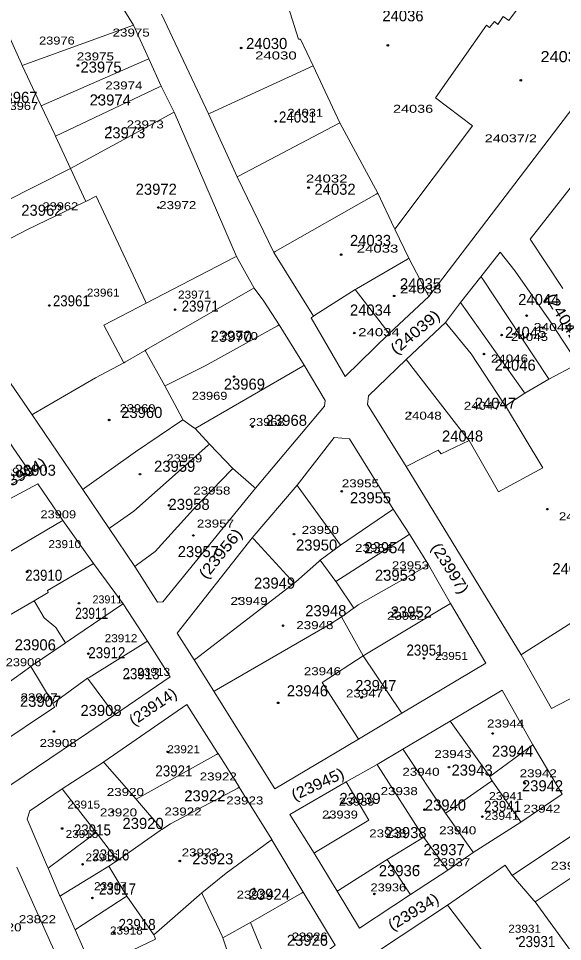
# Model space of a CAD drawing. Extents: x 649608 to 651081, y 237980 to 241202.
# Drawn here: x 650649.6 to 650826.5, y 238207.6 to 238507.5 of the extents above; entities that cross this region are included whole.
import ezdxf

# ---------------------------------------------------------------- set-up
doc = ezdxf.new("R2010")
doc.units = 0
doc.header["$PDMODE"] = 32
doc.header["$PDSIZE"] = 0.5
for name, color, linetype in [('19', 7, 'Continuous'), ('20', 7, 'Continuous'), ('6', 7, 'Continuous')]:
    doc.layers.add(name, color=color, linetype=linetype)
doc.layers.add('3', color=7, linetype='Continuous', lineweight=13)
doc.layers.add('5', color=7, linetype='Continuous', lineweight=13)

msp = doc.modelspace()

# ---------------------------------------------------------------- linework, layer by layer
at = {"layer": '3'}
for p, q in [((650698.955, 238293.605), (650680.881, 238281.304)), ((650833.028, 238244.372), (650810.115, 238229.097))]:
    msp.add_line(p, q, dxfattribs=at)
for points in [[(650687.044, 238505.407), (650681.393, 238514.544), (650666.233, 238537.335), (650662.489, 238538.449), (650636.452, 238531.69), (650637.963, 238526.941), (650615.232, 238519.416)], [(650856.496, 238513.231), (650783.062, 238417.168), (650770.127, 238405.165)], [(650770.127, 238405.165), (650755.807, 238391.194), (650744.776, 238410.239), (650745.518, 238410.844), (650732.624, 238431.532), (650720.683, 238456.081), (650711.443, 238476.563), (650696.151, 238508.876)], [(650734.391, 238407.977), (650729.447, 238415.682), (650726.234, 238419.926), (650720.477, 238430.206), (650700.272, 238477.13), (650695.994, 238485.566), (650691.998, 238494.43), (650687.044, 238505.407)], [(650573.208, 238503.022), (650582.152, 238488.127), (650590.385, 238475.32), (650600.043, 238460.139), (650617.299, 238433.842), (650623.21, 238423.714), (650654.029, 238378.774), (650670.572, 238354.523), (650679.086, 238341.791), (650687.498, 238329.514), (650694.786, 238317.819)], [(650826.605, 238419.813), (650815.978, 238435.816), (650831.358, 238455.416)], [(650775.665, 238361.941), (650763.101, 238382.048), (650763.388, 238384.951), (650775.735, 238396.677), (650788.491, 238408.706), (650793.362, 238415.29), (650800.026, 238423.614), (650806.229, 238431.585)], [(650806.229, 238431.585), (650811.125, 238425.42), (650822.189, 238409.657), (650831.543, 238395.385)], [(650613.787, 238417.512), (650614.114, 238417.034), (650626.967, 238398.087), (650637.752, 238383.107), (650643.512, 238374.619), (650647.922, 238368.026), (650653.658, 238359.639), (650629.394, 238346.511)], [(650726.691, 238354.921), (650749.09, 238381.608), (650749.4, 238383.4), (650742.572, 238394.867), (650734.391, 238407.977)], [(650740.192, 238355.867), (650752.316, 238371.38), (650757.249, 238370.921), (650771.495, 238348.086), (650776.796, 238339.927), (650782.989, 238330), (650790.096, 238317.421)], [(650854.104, 238299.459), (650822.931, 238283.334), (650813.072, 238300.813), (650775.665, 238361.941)], [(650625.649, 238340.229), (650655.926, 238356.355), (650664.083, 238344.431), (650674, 238330.436), (650683.612, 238317.325), (650691.539, 238305.2), (650698.955, 238293.605)], [(650694.786, 238317.819), (650696.602, 238318.019), (650726.691, 238354.921)], [(650701.208, 238307.79), (650725.636, 238338.817), (650740.192, 238355.867)], [(650790.096, 238317.421), (650801.562, 238298.098), (650774.25, 238281.767), (650760.146, 238273.349)], [(650760.146, 238273.349), (650732.936, 238257.22), (650713.263, 238288.77), (650713.175, 238288.91), (650706.764, 238299.126), (650701.208, 238307.79)], [(650680.881, 238281.304), (650647.164, 238258.567), (650641.308, 238270.413), (650635.299, 238282.662), (650625.495, 238302.287)], [(650789.994, 238279.252), (650806.913, 238289.232), (650816.899, 238271.551)], [(650714.531, 238268.662), (650714.348, 238268.952), (650704.332, 238284.588), (650677.373, 238266.01), (650677.247, 238265.929)], [(650737.828, 238248.885), (650756.181, 238259.444), (650766.239, 238265.088), (650774.635, 238270.154), (650789.994, 238279.252)], [(650816.899, 238271.551), (650826.377, 238255.436), (650812.988, 238246.437), (650797.501, 238236.582), (650789.282, 238230.759), (650777.071, 238222.869)], [(650721.411, 238257.749), (650721.356, 238257.837), (650714.531, 238268.662)], [(650677.247, 238265.929), (650663.78, 238257.263), (650663.772, 238257.257)], [(650663.772, 238257.257), (650653.334, 238250.104), (650652.459, 238247.354), (650658.999, 238231.898), (650659.214, 238231.401)], [(650731.986, 238240.663), (650731.957, 238240.711), (650721.411, 238257.749)], [(650777.071, 238222.869), (650760.508, 238211.93), (650753.271, 238223.978), (650745.728, 238236.33), (650737.828, 238248.885)], [(650733.752, 238192.67), (650752.648, 238206.409), (650742.2, 238223.611), (650731.986, 238240.663)], [(650649.081, 238231.778), (650661.143, 238204.909), (650661.217, 238204.732)], [(650659.214, 238231.401), (650662.994, 238222.68), (650663.128, 238222.38), (650668.008, 238211.416), (650673.734, 238198.611)], [(650810.115, 238229.097), (650807.908, 238232.424), (650789.131, 238219.424)], [(650789.131, 238219.424), (650766.398, 238204.401), (650792.759, 238167.518), (650815.522, 238184.763), (650833.498, 238198.629)]]:
    msp.add_lwpolyline(points, dxfattribs=at)
at = {"layer": '5'}
for p, q in [((650666.513, 238458.735), (650661.677, 238469.292)), ((650666.513, 238458.735), (650644.862, 238447.851)), ((650674.685, 238390.795), (650683.873, 238395.683))]:
    msp.add_line(p, q, dxfattribs=at)
for points in [[(650716.197, 238514.45), (650716.697, 238514.578), (650735.331, 238519.332), (650737.208, 238511.711), (650740.707, 238500.782), (650741.379, 238500.793), (650745.427, 238492.156)], [(650815.76, 238515.874), (650815.392, 238515.374), (650809.118, 238506.861), (650807.289, 238508.15), (650805.53, 238505.605), (650804.445, 238506.55), (650802.807, 238504.638), (650801.776, 238505.381)], [(650656.967, 238479.117), (650656.732, 238479.617), (650650.781, 238492.275), (650687.044, 238505.407)], [(650801.776, 238505.381), (650785.213, 238481.741), (650797.262, 238472.641), (650771.985, 238439.041), (650776.594, 238429.62)], [(650650.781, 238492.275), (650650.557, 238492.775), (650646.354, 238502.163), (650647.011, 238502.484)], [(650656.967, 238479.117), (650691.498, 238494.211), (650691.998, 238494.43)], [(650745.427, 238492.156), (650711.943, 238476.792), (650711.443, 238476.563)], [(650771.985, 238439.041), (650771.748, 238439.541), (650766.436, 238450.76), (650754.133, 238473.618), (650745.427, 238492.156)], [(650661.677, 238469.292), (650695.494, 238485.329), (650695.994, 238485.566)], [(650661.677, 238469.292), (650661.437, 238469.792), (650656.967, 238479.117)], [(650700.272, 238477.13), (650699.772, 238476.858), (650666.513, 238458.735), (650671.477, 238448.077)], [(650754.133, 238473.618), (650753.633, 238473.356), (650721.183, 238456.343), (650720.683, 238456.081)], [(650671.477, 238448.077), (650674.855, 238449.74), (650690.912, 238415.563), (650691.147, 238415.063)], [(650766.436, 238450.76), (650765.936, 238450.476), (650733.124, 238431.816), (650732.624, 238431.532)], [(650671.477, 238448.077), (650670.977, 238447.836), (650652.591, 238438.983), (650623.71, 238423.974), (650623.21, 238423.714)], [(650691.147, 238415.063), (650719.977, 238429.948), (650720.477, 238430.206)], [(650776.594, 238429.62), (650776.094, 238429.329), (650759.56, 238419.704), (650759.06, 238419.413)], [(650776.594, 238429.62), (650782.802, 238417.668), (650783.062, 238417.168)], [(650822.125, 238390.345), (650821.793, 238390.845), (650800.358, 238423.114), (650800.026, 238423.614)], [(650690.784, 238399.665), (650691.284, 238399.951), (650725.734, 238419.64), (650726.234, 238419.926)], [(650759.06, 238419.413), (650746.018, 238411.16), (650745.518, 238410.844)], [(650770.127, 238405.165), (650769.739, 238405.665), (650759.06, 238419.413)], [(650683.873, 238395.683), (650677.378, 238407.882), (650691.147, 238415.063)], [(650814.267, 238385.733), (650813.913, 238386.233), (650793.716, 238414.79), (650793.362, 238415.29)], [(650697.254, 238388.122), (650697.754, 238388.371), (650710.306, 238394.622), (650733.891, 238407.7), (650734.391, 238407.977)], [(650807.944, 238381.701), (650807.612, 238382.201), (650796.779, 238398.524), (650788.898, 238408.206), (650788.491, 238408.706)], [(650683.873, 238395.683), (650684.373, 238395.971), (650690.784, 238399.665), (650697.254, 238388.122)], [(650796.135, 238370.378), (650795.747, 238370.878), (650776.123, 238396.177), (650775.735, 238396.677)], [(650831.543, 238395.385), (650831.043, 238395.117), (650822.125, 238390.345), (650814.267, 238385.733), (650807.944, 238381.701)], [(650742.572, 238394.867), (650742.072, 238394.578), (650707.018, 238374.328), (650711.712, 238369.224), (650719.315, 238361.29)], [(650674.685, 238390.795), (650654.529, 238379.065), (650654.029, 238378.774)], [(650697.254, 238388.122), (650702.797, 238377.609), (650703.061, 238377.109)], [(650807.944, 238381.701), (650820.149, 238361.544), (650805.688, 238353.757), (650796.135, 238370.378)], [(650703.061, 238377.109), (650687.624, 238366.673), (650671.072, 238354.879), (650670.572, 238354.523)], [(650707.018, 238374.328), (650706.518, 238374.679), (650703.061, 238377.109)], [(650711.712, 238369.224), (650711.212, 238368.78), (650687.176, 238347.413), (650679.586, 238342.138), (650679.086, 238341.791)], [(650796.135, 238370.378), (650787.024, 238366.12), (650786.132, 238367.257), (650776.165, 238362.195), (650775.665, 238361.941)], [(650719.315, 238361.29), (650718.83, 238360.79), (650706.531, 238348.1), (650694.078, 238334.304), (650687.998, 238329.878), (650687.498, 238329.514)], [(650719.315, 238361.29), (650726.191, 238355.353), (650726.691, 238354.921)], [(650740.192, 238355.867), (650740.556, 238355.367), (650754.367, 238336.415)], [(650754.367, 238336.415), (650770.995, 238347.745), (650771.495, 238348.086)], [(650633.06, 238326.261), (650633.56, 238326.554), (650663.583, 238344.138), (650664.083, 238344.431)], [(650725.636, 238338.817), (650726.098, 238338.317), (650739.284, 238324.06)], [(650752.861, 238324.602), (650776.296, 238339.607), (650776.796, 238339.927)], [(650754.367, 238336.415), (650753.867, 238336.048), (650747.736, 238331.55), (650752.861, 238324.602)], [(650654.699, 238318.288), (650659.301, 238321.036), (650659.009, 238321.678), (650673.5, 238330.144), (650674, 238330.436)], [(650739.284, 238324.06), (650739.784, 238324.503), (650747.236, 238331.107), (650747.736, 238331.55)], [(650758.672, 238315.938), (650760.081, 238317.047), (650782.489, 238329.717), (650782.989, 238330)], [(650739.284, 238324.06), (650707.264, 238299.509), (650706.764, 238299.126)], [(650752.861, 238324.602), (650753.196, 238324.102), (650758.672, 238315.938)], [(650642.003, 238311.005), (650642.503, 238311.292), (650654.699, 238318.288)], [(650654.699, 238318.288), (650654.997, 238317.788), (650657.986, 238312.781), (650661.789, 238309.622), (650664.923, 238304.62)], [(650664.923, 238304.62), (650683.112, 238316.985), (650683.612, 238317.325)], [(650790.096, 238317.421), (650789.596, 238317.128), (650786.052, 238315.052), (650761.76, 238300.46)], [(650842.562, 238319.464), (650842.062, 238319.148), (650813.572, 238301.129), (650813.072, 238300.813)], [(650758.672, 238315.938), (650758.172, 238315.584), (650755.178, 238313.468), (650754.678, 238313.114)], [(650713.175, 238288.91), (650713.302, 238288.983), (650751.299, 238310.921), (650754.678, 238313.114), (650761.76, 238300.46)], [(650672.084, 238293.127), (650672.584, 238293.437), (650691.039, 238304.89), (650691.539, 238305.2)], [(650664.923, 238304.62), (650664.423, 238304.283), (650654.096, 238297.323), (650653.596, 238296.986)], [(650761.76, 238300.46), (650748.371, 238291.789), (650759.827, 238273.849), (650760.146, 238273.349)], [(650774.25, 238281.767), (650773.916, 238282.267), (650761.76, 238300.46)], [(650635.299, 238282.662), (650635.799, 238283.032), (650646.025, 238290.6), (650645.528, 238291.118), (650653.596, 238296.986)], [(650653.596, 238296.986), (650660.519, 238285.434), (650660.819, 238284.934)], [(650641.308, 238270.413), (650641.808, 238270.746), (650661.302, 238283.747), (650660.819, 238284.934), (650672.084, 238293.127)], [(650672.084, 238293.127), (650680.509, 238281.804), (650680.881, 238281.304)], [(650802.849, 238261.186), (650790.35, 238278.752), (650789.994, 238279.252)], [(650774.635, 238270.154), (650774.966, 238269.654), (650788.476, 238249.263)], [(650816.899, 238271.551), (650816.399, 238271.182), (650802.849, 238261.186)], [(650687.856, 238253.857), (650714.031, 238268.384), (650714.531, 238268.662)], [(650677.247, 238265.929), (650677.686, 238265.429), (650687.856, 238253.857)], [(650766.239, 238265.088), (650766.56, 238264.588), (650781.429, 238241.445)], [(650802.849, 238261.186), (650803.13, 238260.686), (650803.614, 238259.825)], [(650674.898, 238243.015), (650664.163, 238256.757), (650663.772, 238257.257)], [(650721.411, 238257.749), (650720.911, 238257.484), (650699.038, 238245.894), (650696.273, 238243.978), (650696.203, 238244.06)], [(650756.181, 238259.444), (650756.476, 238258.944), (650763.518, 238246.991), (650746.228, 238236.63), (650745.728, 238236.33)], [(650803.614, 238259.825), (650803.114, 238259.476), (650788.976, 238249.612), (650788.476, 238249.263)], [(650803.614, 238259.825), (650812.638, 238246.937), (650812.988, 238246.437)], [(650696.203, 238244.06), (650688.282, 238253.357), (650687.856, 238253.857)], [(650788.476, 238249.263), (650797.145, 238237.082), (650797.501, 238236.582)], [(650659.214, 238231.401), (650659.714, 238231.771), (650674.898, 238243.015)], [(650681.808, 238233.895), (650675.277, 238242.515), (650674.898, 238243.015)], [(650696.203, 238244.06), (650695.703, 238243.707), (650681.808, 238233.895)], [(650731.986, 238240.663), (650731.486, 238240.3), (650717.107, 238229.871), (650709.194, 238223.416), (650693.647, 238209.825), (650684.852, 238222.355)], [(650781.429, 238241.445), (650780.929, 238241.142), (650769.475, 238234.211)], [(650781.429, 238241.445), (650788.915, 238231.259), (650789.282, 238230.759)], [(650681.808, 238233.895), (650681.308, 238233.576), (650678.984, 238232.092)], [(650769.475, 238234.211), (650768.975, 238233.895), (650753.771, 238224.294), (650753.271, 238223.978)], [(650769.475, 238234.211), (650776.736, 238223.369), (650777.071, 238222.869)], [(650678.984, 238232.092), (650678.966, 238232.08), (650663.628, 238222.686), (650663.128, 238222.38)], [(650684.852, 238222.355), (650679.285, 238231.592), (650678.984, 238232.092)], [(650817.634, 238220.462), (650829.028, 238228.095), (650831.481, 238224.416), (650841.05, 238231.01), (650841.55, 238231.355)], [(650817.634, 238220.462), (650817.199, 238220.962), (650810.55, 238228.597), (650810.115, 238229.097)], [(650684.852, 238222.355), (650684.352, 238222.03), (650668.508, 238211.741), (650668.008, 238211.416)], [(650716.041, 238208.793), (650715.807, 238209.293), (650709.428, 238222.916), (650709.194, 238223.416)], [(650742.2, 238223.611), (650741.7, 238223.325), (650725.102, 238213.833)], [(650815.522, 238184.763), (650815.141, 238185.263), (650789.512, 238218.924), (650789.131, 238219.424)], [(650833.498, 238198.629), (650833.135, 238199.129), (650817.634, 238220.462)], [(650725.102, 238213.833), (650724.602, 238213.555), (650716.041, 238208.793)], [(650725.102, 238213.833), (650733.548, 238193.17), (650733.752, 238192.67)], [(650673.734, 238198.611), (650674.234, 238198.851), (650694.13, 238208.411), (650693.818, 238209.325), (650693.647, 238209.825)], [(650716.041, 238208.793), (650723.624, 238186.162), (650723.792, 238185.662)]]:
    msp.add_lwpolyline(points, dxfattribs=at)
at = {"layer": '6'}
for p in [(650722.018, 238497.947), (650769.738, 238498.79), (650668.913, 238492.262), (650812.989, 238487.434), (650675.713, 238481.861), (650733.222, 238474.118), (650679.418, 238472.15), (650743.924, 238452.575), (650695.101, 238446.096), (650754.547, 238430.802), (650771.788, 238417.392), (650659.648, 238414.257), (650700.551, 238412.944), (650814.85, 238410.965), (650712.836, 238404.024), (650758.827, 238405.303), (650806.739, 238404.673), (650801.019, 238398.495), (650719.74, 238391.152), (650797.972, 238381.231), (650679.107, 238377.094), (650777.01, 238379.309), (650725.726, 238374.894), (650689.102, 238359.45), (650754.748, 238353.897), (650698.569, 238349.369), (650821.623, 238348.099), (650706.489, 238339.554), (650739.198, 238339.963), (650762.735, 238336.344), (650652.447, 238327.718), (650768.697, 238327.932), (650669.308, 238317.528), (650721.329, 238318.971), (650772.013, 238315.23), (650735.674, 238310.23), (650672.361, 238301.129), (650781.506, 238299.594), (650685.361, 238293.252), (650761.154, 238286.904), (650734.055, 238285.167), (650661.123, 238275.847), (650803.852, 238275.209), (650698.105, 238269.222), (650789.603, 238264.257), (650814.24, 238258.994), (650705.504, 238256.32), (650680.364, 238249.912), (650750.723, 238247.887), (650781.663, 238250.456), (650800.491, 238248.203), (650663.805, 238244.329), (650769.431, 238244.533), (650702.072, 238233.787), (650670.448, 238232.697), (650779.553, 238232.157), (650726.167, 238224.728), (650673.667, 238221.754), (650765.376, 238223.07), (650680.805, 238210.483), (650739.513, 238208.14), (650811.818, 238208.593)]:
    msp.add_point(p, dxfattribs=at)

# ---------------------------------------------------------------- texts
at = {"layer": '19'}
for s, p in [('24036', (650767.957, 238506.6)), ('24030', (650723.63, 238497.601)), ('23975', (650669.764, 238489.921)), ('23967', (650642.402, 238480.109)), ('23974', (650672.756, 238479.256)), ('23973', (650677.459, 238468.591)), ('23972', (650687.719, 238450.247)), ('24032', (650745.861, 238450.248)), ('23962', (650650.525, 238443.421)), ('24033', (650757.403, 238433.61)), ('24035', (650773.649, 238419.532)), ('24044', (650812.123, 238414.411)), ('24034', (650757.403, 238411)), ('24045', (650807.849, 238403.746)), ('23970', (650712.088, 238402.466)), ('24046', (650804.429, 238393.081)), ('23969', (650716.386, 238386.917)), ('24047', (650798.016, 238380.709)), ('23960', (650683.016, 238377.723)), ('23968', (650730.042, 238375.163)), ('24048', (650787.329, 238370.044)), ('23903', (650648.388, 238358.951)), ('23959', (650693.704, 238360.232)), ('23955', (650757.404, 238349.992)), ('23958', (650698.406, 238347.86)), ('23950', (650739.875, 238334.634)), ('23957', (650701.399, 238332.502)), ('23954', (650762.105, 238333.781)), ('24049', (650823.24, 238326.956)), ('23953', (650765.527, 238324.822)), ('23949', (650726.196, 238322.262)), ('23948', (650742.867, 238313.304)), ('23952', (650770.657, 238312.877)), ('23906', (650648.388, 238302.212)), ('23946', (650736.883, 238287.281)), ('23947', (650759.114, 238288.987)), ('23907', (650650.098, 238283.868)), ('23908', (650669.763, 238280.882)), ('23944', (650803.574, 238267.657)), ('23943', (650790.437, 238261.501)), ('23942', (650813.349, 238256.412)), ('23922', (650703.538, 238253.153)), ('23939', (650753.983, 238252.299)), ('23940', (650781.771, 238250.166)), ('23920', (650683.444, 238244.194)), ('23938', (650768.946, 238241.208)), ('23937', (650781.344, 238235.662)), ('23923', (650706.103, 238232.676)), ('23936', (650766.808, 238228.836)), ('23924', (650724.485, 238221.157)), ('23926', (650736.883, 238206.226))]:
    msp.add_text(s, height=3.6, dxfattribs=at).set_placement(p)
for s, width, p in [('24037/2', 1.1, (650819.392, 238493.334)), ('24031', 0.9, (650734.318, 238473.711)), ('23961', 0.9, (650660.785, 238413.985)), ('23971', 0.9, (650702.682, 238412.278)), ('23910', 0.9, (650651.807, 238324.822)), ('23911', 0.8, (650668.054, 238312.451)), ('23912', 0.9, (650672.329, 238299.652)), ('23951', 0.9, (650775.787, 238300.505)), ('23913', 0.9, (650683.444, 238292.827)), ('23921', 0.9, (650694.132, 238261.258)), ('23941', 0.9, (650801.01, 238249.74)), ('23915', 0.9, (650667.626, 238242.061)), ('23916', 0.9, (650673.611, 238233.955)), ('23917', 0.9, (650675.748, 238222.864)), ('23918', 0.9, (650682.161, 238211.345)), ('23931', 0.9, (650812.124, 238205.799))]:
    msp.add_text(s, height=3.6, dxfattribs=dict(at, width=width)).set_placement(p)
for s, rotation, width, p in [('(24042)', 301.484, 1.15, (650820.818, 238416.872)), ('(24039)', 40.043, 1.15, (650772.436, 238398.14)), ('(23904)', 29.304, 1.1, (650643.18, 238353.038)), ('(23956)', 51.277, 1.15, (650710.7, 238325.097)), ('(23997)', 301.854, 1.1, (650783.644, 238335.703)), ('(23914)', 34.121, 1.05, (650687.09, 238277.572)), ('(23945)', 24.73, 1.1, (650739.37, 238253.303)), ('(23934)', 31.21, 1.1, (650771.138, 238211.032))]:
    msp.add_text(s, height=3.6, rotation=rotation, dxfattribs=dict(at, width=width)).set_placement(p)
at = {"layer": '20'}
for s, width, p in [('23975', 1.25, (650680.217, 238501.643)), ('23976', 1.2, (650656.298, 238499.049)), ('23975', 1.25, (650668.579, 238493.894)), ('24030 ', 1.4, (650726.556, 238494.211)), ('23974', 1.25, (650677.852, 238484.474)), ('23967', 1.2, (650644.394, 238477.799)), ('24036 ', 1.35, (650771.42, 238476.881)), ('24031 ', 1.2, (650737.054, 238475.583)), ('23973', 1.25, (650684.781, 238471.806)), ('24037/2', 1.35, (650801.237, 238467.273)), ('24032 ', 1.4, (650743.08, 238454.21)), ('23962', 1.2, (650657.426, 238445.212)), ('23972', 1.25, (650695.358, 238445.576)), ('24033 ', 1.4, (650759.608, 238431.455)), ('23961', 1.1, (650671.842, 238417.154)), ('23971', 1.1, (650701.506, 238416.515)), ('24035 ', 1.4, (650773.673, 238418.219)), ('24044', 1.3, (650817.175, 238405.965)), ('23970', 1.25, (650715.396, 238403.035)), ('24034 ', 1.4, (650760.092, 238404.297)), ('24045', 1.25, (650809.759, 238402.764)), ('24046', 1.25, (650803.238, 238395.73)), ('23969', 1.2, (650705.957, 238383.626)), ('23960', 1.2, (650682.536, 238379.589)), ('24047', 1.25, (650794.422, 238380.382)), ('23968', 1.2, (650724.558, 238375.1)), ('24048', 1.25, (650775.162, 238377.181)), ('23959', 1.2, (650697.753, 238363.305)), ('23903', 1.25, (650642.705, 238358.951)), ('23955', 1.25, (650754.762, 238355.177)), ('23958', 1.25, (650706.444, 238352.829)), ('23909', 1.2, (650656.759, 238345.104)), ('24049', 1.25, (650825.35, 238344.467)), ('23957', 1.25, (650707.626, 238342.11)), ('23950', 1.25, (650741.724, 238340.056)), ('23910', 1.1, (650659.348, 238335.434)), ('23954', 1.25, (650759.064, 238334.172)), ('23953', 1.25, (650771.039, 238328.546)), ('23949', 1.25, (650718.547, 238316.964)), ('23952', 1.25, (650769.439, 238312.139)), ('23948', 1.25, (650739.958, 238309.108)), ('23912', 1.1, (650677.645, 238304.856)), ('23906', 1.2, (650645.458, 238297.052)), ('23951', 1.1, (650785.115, 238299.089)), ('23913', 1.1, (650688.277, 238293.925)), ('23946', 1.25, (650742.41, 238294.131)), ('23907', 1.25, (650650.265, 238285.632)), ('23947', 1.25, (650756.103, 238286.922)), ('23944', 1.25, (650801.986, 238277.141)), ('23908', 1.25, (650656.469, 238270.814)), ('23921', 1.1, (650697.99, 238268.776)), ('23943', 1.25, (650784.87, 238267.253)), ('23940', 1.25, (650774.461, 238261.454)), ('23942', 1.25, (650812.597, 238260.978)), ('23922', 1.25, (650708.539, 238259.934)), ('23920', 1.25, (650678.334, 238254.895)), ('23938', 1.25, (650767.383, 238255.179)), ('23923', 1.25, (650717.175, 238252.138)), ('23939', 1.2, (650753.784, 238251.757)), ('23941', 1.15, (650802.62, 238253.563)), ('23915', 1.1, (650665.521, 238250.808)), ('23922', 1.25, (650697.076, 238248.559)), ('23942', 1.25, (650813.786, 238249.463)), ('23920', 1.25, (650676.092, 238248.263)), ('23939', 1.2, (650748.375, 238247.564)), ('23941', 1.15, (650801.21, 238247.158)), ('23915', 1.1, (650664.958, 238241.258)), ('23938', 1.25, (650763.67, 238241.447)), ('23940', 1.25, (650786.408, 238242.434)), ('23916', 1.1, (650671.413, 238233.661)), ('23923', 1.25, (650702.684, 238235.24)), ('23937', 1.25, (650784.437, 238232.075)), ('23932/2', 1.35, (650822.712, 238230.938)), ('23917', 1.1, (650674.193, 238224.289)), ('23924', 1.25, (650720.535, 238221.535)), ('23936', 1.2, (650764.092, 238223.886)), ('23822', 1.25, (650649.735, 238213.559)), ('23820', 1.25, (650638.523, 238210.91)), ('23918', 1.1, (650679.378, 238209.884)), ('23931', 1.1, (650808.898, 238210.463)), ('23926', 1.2, (650738.522, 238207.92))]:
    msp.add_text(s, height=2.6, dxfattribs=dict(at, width=width)).set_placement(p)
msp.add_text('23911', height=2.6, dxfattribs=at).set_placement((650673.697, 238317.474))

doc.saveas('drawing.dxf')
